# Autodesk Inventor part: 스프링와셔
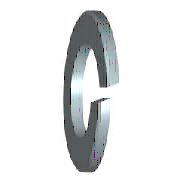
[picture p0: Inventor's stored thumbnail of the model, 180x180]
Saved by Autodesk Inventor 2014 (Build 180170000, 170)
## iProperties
Created: 2012-02
Part Number: 스프링와셔
Material: 강철, 연강
Description: 스프링 와셔
Document SubType Name: Modeling
Standard: JIS B 1251
Designer: mduedu
Standards Organization: JIS
Language: ko-KR
Size Designation: 번호 2 4
Categories: <MemberInstance><Categories><Category DisplayName="조임쇠" InternalName="e4da775c-781d-43d5-af7c-5136215cf5a6" Mnemonic="FSTN"><Category DisplayName="와셔" InternalN
Density: 7.86 g/cm^3
Appearance: 파란색 - 벽 페인트 - 광택
Mass: 0.247271 g
Surface Area: 1.02615 cm^2
Volume: 0.0314594 cm^3
IsCustomPart: 1
Author: mduedu
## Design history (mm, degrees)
sketch "스케치1"
  geometry: C1 r 3.8 at (0, 0); C2 r 2.05 at (0, 0); 1 further point
  constraints: 2 centre point, 2 coincident
  dimensions: "d0" = 4.1 diameter of C2 (= SD1); "d1" = 7.6 diameter of C1 (= SD2)
extrude "본체" new body sketch "스케치1" distance "d2" = 1 (= SD); taper "d3" = 0 deg
sketch "스케치2"
  geometry: L1 (0, -2.05)-(0, 2.05) reference; L2 (1, 3.8)-(1, -3.8) reference; L3 (-1.2, 0)-(7.2, 0) reference; L4 (0, -0.2)-(1, 0.164); L5 (0, 0.2)-(1, 0.564)
  constraints: 4 end point, 4 point on line, 1 parallel
  dimensions: "d4" = 0.2 distance from line of L3 L4.start (= 0.2 x SD); "d5" = 0.2 distance from line of L3 L5.start (= 0.2 x SD); "d6" = 70 deg angle of L2 L4 (= FAWI)
extrude "절단부" cut sketch "스케치2" stored distance "d7" = 1 (= SD); taper "d8" = 0 deg
workaxis "Work Axis1"
workplane "Work Plane1"
body "Solid1"
other parameters: "SD1" = 4.1 [user parameter; used in 1 equation term], "SD2" = 7.6 [user parameter; used in 1 equation term], "SD" = 1 [user parameter; used in 4 equation terms], "FAWI" = 70 deg [user parameter; used in 1 equation term], "d9" = 0, "d10" = 0, "d11" = 0, "d12" = 0, "SDI" = 1.4 [user parameter], "NND" = 4 [user parameter]
